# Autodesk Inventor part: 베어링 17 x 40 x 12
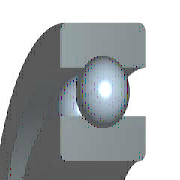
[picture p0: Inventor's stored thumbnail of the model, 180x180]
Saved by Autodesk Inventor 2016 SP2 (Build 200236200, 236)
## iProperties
IsCustomPart: 1
Created: 2012-02
Part Number: 베어링 17 x 40 x 12
Material: 강철, 연강
Description: 깊은 그루브 볼 베어링
Document SubType Name: Modeling
Standard: KS B 2023
Designer: mduedu
Standards Organization: KS
Language: ko-KR
Size Designation: 6203 - 17 x 40 x 12
Categories: <MemberInstance><Categories><Category DisplayName="샤프트 부품" InternalName="7f7aeb1f-a693-4053-b835-cee3144e0d98" Mnemonic="SHFT"><Category DisplayName="베어링" Inter
Density: 1 g/cm^3
Appearance: 노란색
Author: mduedu
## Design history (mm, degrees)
sketch "스케치" dims "d0" = 5.98 (= -0.26 x WD + 0.26 x BD)
  geometry: L1 (3.01, 14.25)-(8.99, 14.25); L2 (6, 14.25)-(6, 11.26); L3 (6, 14.25)-(6, 17.24); L4 (3.778, 12.249)-(0, 12.249); L5 (0, 8.5)-(12, 8.5); L6 (3.778, 16.251)-(0, 16.251); L7 (0, 20)-(12, 20); L8 (12, 8.5)-(12, 12.249); L9 (8.222, 12.249)-(12, 12.249); L10 (8.222, 16.251)-(12, 16.251); L11 (12, 20)-(12, 16.251); L12 (-1.4, 0)-(8.4, 0) reference; L13 (0, -0.3)-(0, 5.3) reference
  constraints: 22 end point, 4 point on line, 2 collinear, 2 perpendicular, 2 symmetric about line, 1 midpoint, 1 parallel, 14 other
  dimensions: "d9" = 17 diameter of L5 L12 (= WD); "d11" = 40 diameter of L7 L12 (= BD); "d12" = 12 distance between parallel lines of L8 L13 (= KB); "d13" = 24.498 diameter of L9 L12 (= 0.326 x BD + 0.674 x WD)
revolve "본체" stored, may be unused: angle "d6" = 90 deg
revolve "볼" stored, may be unused: angle "d7" = 90 deg
pattern_circular "IDS_ARRAYBALL[SIMPL:T]" dims angle "d3" = 360 deg
body "Solid1"
fillet "모깎기1" dims "d1" = 0.6 (= KRS)
other parameters: "WD" = 17 [user parameter; used in 5 equation terms], "BD" = 40 [user parameter; used in 5 equation terms], "KB" = 12 [user parameter; used in 1 equation term], "KRS" = 0.6 [user parameter; used in 1 equation term], "d4" = 0, "d5" = 0, "d8" = 0, "d14" = 0, "d15" = 0, "BBA" = 0 [user parameter], "BC0" = 4750000 [user parameter], "BC" = 9560000 [user parameter], "WR" = 8.5 (= 0.5 x WD) [user parameter]
